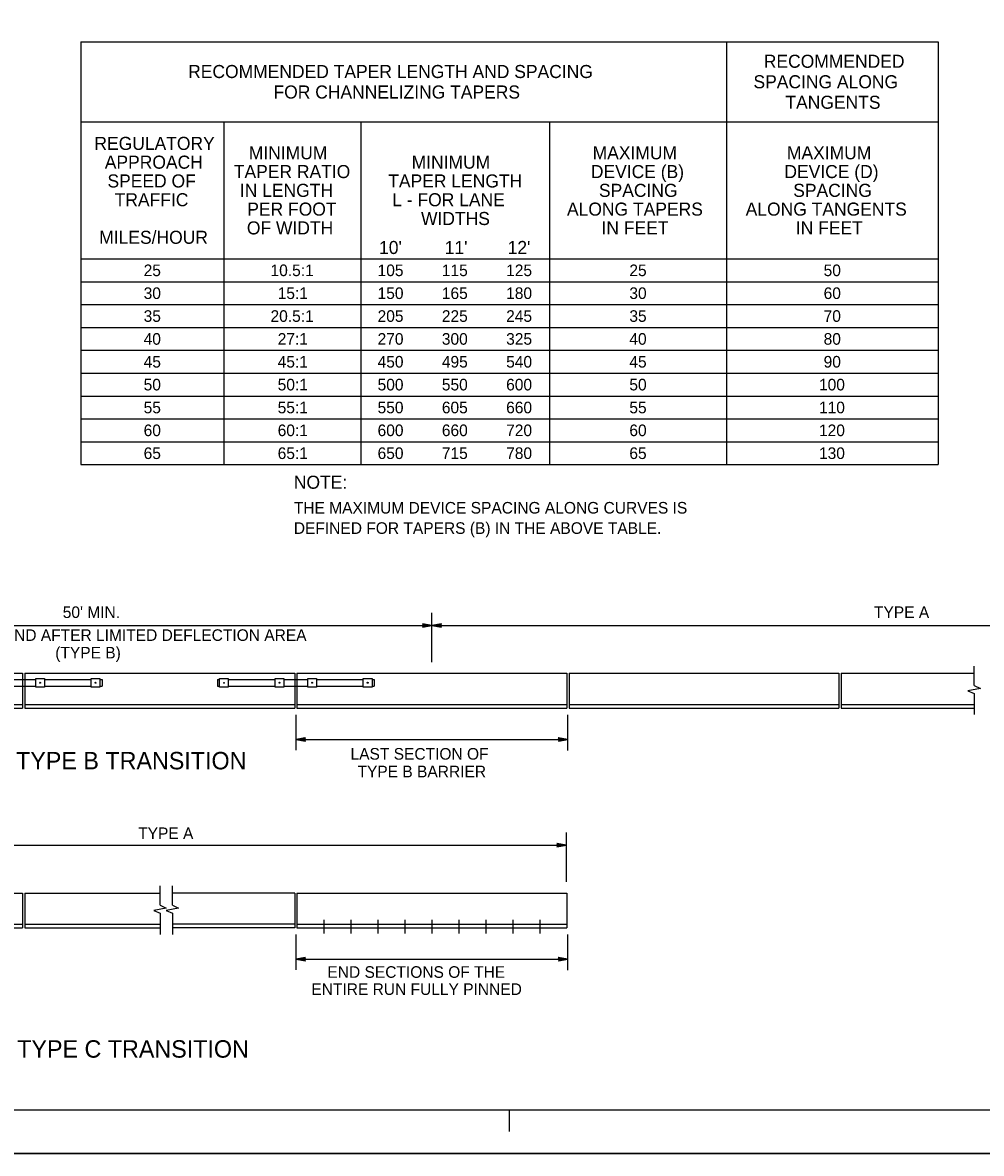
# Model space of a CAD drawing. Extents: x 499909 to 500993, y 502505 to 503165.
# Drawn here: x 500297.3 to 500627.6, y 502505 to 502894.5 of the extents above; entities that cross this region are included whole.
import ezdxf

# ---------------------------------------------------------------- set-up
doc = ezdxf.new("R2010")
doc.units = 0
for name, color, linetype in [('1', 7, 'Continuous'), ('24', 7, 'Continuous'), ('3', 7, 'Continuous'), ('39', 7, 'Continuous'), ('41', 7, 'Continuous'), ('5', 7, 'Continuous')]:
    doc.layers.add(name, color=color, linetype=linetype)

msp = doc.modelspace()

# ---------------------------------------------------------------- linework, layer by layer
at = {"layer": '1'}
for p, q in [((500000, 502520), (500990, 502520)), ((500465, 502512.5), (500465, 502520)), ((500993, 502505), (499944.83, 502505))]:
    msp.add_line(p, q, dxfattribs=at)
at = {"layer": '24'}
for points in [[(500438.31, 502686.89), (500434.99, 502687.48), (500435.78, 502686.89), (500435, 502686.31), (500438.31, 502686.89), (500438.09, 502686.88), (500435.08, 502687.43), (500435.84, 502686.88), (500435.14, 502686.36), (500437.97, 502686.87), (500437.86, 502686.89), (500435.28, 502687.35), (500435.86, 502686.88), (500435.26, 502686.43), (500437.81, 502686.89), (500437.7, 502686.87), (500435.44, 502687.28), (500435.88, 502686.89), (500435.44, 502686.48), (500437.38, 502686.87), (500437.19, 502686.87), (500435.61, 502687.2), (500435.92, 502686.9), (500435.59, 502686.57), (500437.16, 502686.89), (500436.98, 502686.9), (500435.79, 502687.1), (500436.02, 502686.87), (500435.77, 502686.64), (500436.82, 502686.89), (500436.65, 502686.91), (500435.94, 502687.04), (500436.05, 502686.88), (500435.86, 502686.7), (500436.56, 502686.89), (500436.1, 502687), (500436.16, 502686.87), (500435.96, 502686.75), (500436.45, 502686.87), (500436.14, 502686.95), (500436.27, 502686.85), (500436.12, 502686.79), (500436.27, 502686.88), (500436.19, 502686.9)], [(500438.31, 502686.89), (500441.63, 502686.3), (500440.84, 502686.89), (500441.62, 502687.47), (500438.31, 502686.89), (500438.53, 502686.9), (500441.54, 502686.34), (500440.78, 502686.9), (500441.48, 502687.42), (500438.65, 502686.91), (500438.76, 502686.89), (500441.34, 502686.43), (500440.76, 502686.9), (500441.36, 502687.35), (500438.81, 502686.89), (500438.92, 502686.91), (500441.18, 502686.5), (500440.74, 502686.89), (500441.19, 502687.29), (500439.24, 502686.91), (500439.43, 502686.91), (500441.01, 502686.58), (500440.7, 502686.88), (500441.03, 502687.21), (500439.46, 502686.89), (500439.64, 502686.88), (500440.83, 502686.68), (500440.6, 502686.91), (500440.85, 502687.13), (500439.8, 502686.89), (500439.97, 502686.87), (500440.68, 502686.74), (500440.57, 502686.9), (500440.76, 502687.07), (500440.06, 502686.89), (500440.52, 502686.78), (500440.46, 502686.91), (500440.66, 502687.03), (500440.18, 502686.91), (500440.48, 502686.83), (500440.35, 502686.93), (500440.5, 502686.99), (500440.35, 502686.9), (500440.43, 502686.88)], [(500391.37, 502647.58), (500394.7, 502646.99), (500393.9, 502647.58), (500394.68, 502648.16), (500391.37, 502647.58), (500391.6, 502647.59), (500394.61, 502647.04), (500393.84, 502647.59), (500394.55, 502648.11), (500391.71, 502647.6), (500391.82, 502647.58), (500394.4, 502647.12), (500393.82, 502647.59), (500394.42, 502648.04), (500391.88, 502647.58), (500391.99, 502647.6), (500394.24, 502647.19), (500393.8, 502647.58), (500394.25, 502647.98), (500392.31, 502647.6), (500392.49, 502647.6), (500394.07, 502647.27), (500393.77, 502647.57), (500394.1, 502647.9), (500392.53, 502647.58), (500392.71, 502647.57), (500393.89, 502647.37), (500393.66, 502647.6), (500393.91, 502647.82), (500392.87, 502647.58), (500393.04, 502647.56), (500393.75, 502647.43), (500393.63, 502647.59), (500393.83, 502647.76), (500393.12, 502647.58), (500393.59, 502647.47), (500393.52, 502647.6), (500393.72, 502647.72), (500393.24, 502647.6), (500393.54, 502647.52), (500393.42, 502647.62), (500393.56, 502647.68), (500393.42, 502647.59), (500393.49, 502647.57)], [(500485.15, 502647.58), (500481.83, 502648.17), (500482.62, 502647.58), (500481.85, 502647), (500485.15, 502647.58), (500484.93, 502647.57), (500481.92, 502648.12), (500482.69, 502647.57), (500481.98, 502647.05), (500484.82, 502647.56), (500484.7, 502647.58), (500482.13, 502648.04), (500482.7, 502647.57), (500482.11, 502647.12), (500484.65, 502647.58), (500484.54, 502647.56), (500482.29, 502647.97), (500482.73, 502647.58), (500482.28, 502647.17), (500484.22, 502647.56), (500484.03, 502647.56), (500482.46, 502647.89), (500482.76, 502647.59), (500482.43, 502647.26), (500484, 502647.58), (500483.82, 502647.59), (500482.64, 502647.79), (500482.86, 502647.56), (500482.62, 502647.33), (500483.66, 502647.58), (500483.49, 502647.6), (500482.78, 502647.73), (500482.9, 502647.57), (500482.7, 502647.39), (500483.41, 502647.58), (500482.94, 502647.69), (500483.01, 502647.56), (500482.8, 502647.44), (500483.29, 502647.56), (500482.98, 502647.64), (500483.11, 502647.54), (500482.97, 502647.48), (500483.11, 502647.57), (500483.03, 502647.59)], [(500484.68, 502611.2), (500481.35, 502611.79), (500482.15, 502611.2), (500481.37, 502610.62), (500484.68, 502611.2), (500484.46, 502611.19), (500481.45, 502611.74), (500482.21, 502611.19), (500481.5, 502610.67), (500484.34, 502611.18), (500484.23, 502611.2), (500481.65, 502611.66), (500482.23, 502611.19), (500481.63, 502610.74), (500484.18, 502611.2), (500484.07, 502611.18), (500481.81, 502611.59), (500482.25, 502611.2), (500481.8, 502610.8), (500483.74, 502611.18), (500483.56, 502611.18), (500481.98, 502611.51), (500482.29, 502611.21), (500481.96, 502610.88), (500483.52, 502611.2), (500483.35, 502611.21), (500482.16, 502611.41), (500482.39, 502611.18), (500482.14, 502610.96), (500483.18, 502611.2), (500483.02, 502611.22), (500482.3, 502611.35), (500482.42, 502611.19), (500482.23, 502611.02), (500482.93, 502611.2), (500482.46, 502611.31), (500482.53, 502611.18), (500482.33, 502611.06), (500482.81, 502611.18), (500482.51, 502611.26), (500482.63, 502611.16), (500482.49, 502611.1), (500482.63, 502611.19), (500482.56, 502611.21)], [(500391.37, 502571.89), (500394.7, 502571.3), (500393.9, 502571.89), (500394.68, 502572.47), (500391.37, 502571.89), (500391.6, 502571.9), (500394.61, 502571.35), (500393.84, 502571.9), (500394.55, 502572.42), (500391.71, 502571.91), (500391.82, 502571.89), (500394.4, 502571.43), (500393.82, 502571.9), (500394.42, 502572.35), (500391.88, 502571.89), (500391.99, 502571.91), (500394.24, 502571.5), (500393.8, 502571.89), (500394.25, 502572.3), (500392.31, 502571.91), (500392.49, 502571.91), (500394.07, 502571.58), (500393.77, 502571.88), (500394.1, 502572.21), (500392.53, 502571.89), (500392.71, 502571.88), (500393.89, 502571.68), (500393.66, 502571.91), (500393.91, 502572.14), (500392.87, 502571.89), (500393.04, 502571.87), (500393.75, 502571.74), (500393.63, 502571.9), (500393.83, 502572.08), (500393.12, 502571.89), (500393.59, 502571.78), (500393.52, 502571.91), (500393.72, 502572.03), (500393.24, 502571.91), (500393.54, 502571.83), (500393.42, 502571.93), (500393.56, 502571.99), (500393.42, 502571.9), (500393.49, 502571.88)], [(500485.15, 502571.89), (500481.83, 502572.48), (500482.62, 502571.89), (500481.85, 502571.31), (500485.15, 502571.89), (500484.93, 502571.88), (500481.92, 502572.43), (500482.69, 502571.88), (500481.98, 502571.36), (500484.82, 502571.87), (500484.7, 502571.89), (500482.13, 502572.35), (500482.7, 502571.88), (500482.11, 502571.43), (500484.65, 502571.89), (500484.54, 502571.87), (500482.29, 502572.28), (500482.73, 502571.89), (500482.28, 502571.49), (500484.22, 502571.87), (500484.03, 502571.87), (500482.46, 502572.2), (500482.76, 502571.9), (500482.43, 502571.57), (500484, 502571.89), (500483.82, 502571.9), (500482.64, 502572.1), (500482.86, 502571.87), (500482.62, 502571.65), (500483.66, 502571.89), (500483.49, 502571.91), (500482.78, 502572.04), (500482.9, 502571.88), (500482.7, 502571.71), (500483.41, 502571.89), (500482.94, 502572), (500483.01, 502571.87), (500482.8, 502571.75), (500483.29, 502571.87), (500482.98, 502571.95), (500483.11, 502571.85), (500482.97, 502571.79), (500483.11, 502571.88), (500483.03, 502571.9)]]:
    msp.add_lwpolyline(points, dxfattribs=at)
at = {"layer": '3'}
for p, q in [((500073.16, 502686.89), (500765.89, 502686.89)), ((500204.29, 502670.39), (500297.28, 502670.39)), ((500297.28, 502670.39), (500297.28, 502668.24)), ((500298.04, 502670.39), (500298.04, 502668.24)), ((500298.04, 502670.39), (500391.02, 502670.39)), ((500391.02, 502670.39), (500391.02, 502668.24)), ((500391.78, 502670.39), (500391.78, 502668.24)), ((500391.78, 502670.39), (500484.77, 502670.39)), ((500484.77, 502670.39), (500484.77, 502668.24)), ((500485.52, 502670.39), (500485.52, 502668.24)), ((500485.52, 502670.39), (500578.51, 502670.39)), ((500578.51, 502670.39), (500578.51, 502668.24)), ((500579.26, 502670.39), (500579.26, 502668.24)), ((500579.26, 502670.39), (500625.1, 502670.39)), ((500625.1, 502666.2), (500625.1, 502672.89)), ((500293.54, 502668.24), (500301.79, 502668.24)), ((500293.54, 502665.99), (500301.79, 502665.99)), ((500297.28, 502668.23), (500297.28, 502665.99)), ((500297.28, 502665.99), (500297.28, 502658.4)), ((500298.04, 502668.23), (500298.04, 502666)), ((500298.04, 502668.23), (500298.04, 502666)), ((500298.04, 502665.99), (500298.04, 502658.4)), ((500304.79, 502668.24), (500320.91, 502668.24)), ((500304.79, 502665.99), (500320.91, 502665.99)), ((500323.91, 502668.24), (500324.66, 502668.24)), ((500323.91, 502665.99), (500324.66, 502665.99)), ((500324.66, 502668.24), (500324.66, 502665.99)), ((500364.4, 502668.24), (500364.4, 502665.99)), ((500364.4, 502668.24), (500365.15, 502668.24)), ((500364.4, 502665.99), (500365.15, 502665.99)), ((500368.15, 502668.24), (500384.28, 502668.24)), ((500368.15, 502665.99), (500384.28, 502665.99)), ((500387.28, 502668.24), (500395.53, 502668.24)), ((500387.28, 502665.99), (500395.53, 502665.99)), ((500391.02, 502668.23), (500391.02, 502665.99)), ((500391.02, 502665.99), (500391.02, 502658.4)), ((500391.78, 502668.23), (500391.78, 502666)), ((500391.78, 502668.23), (500391.78, 502666)), ((500391.78, 502665.99), (500391.78, 502658.4)), ((500398.53, 502668.24), (500414.65, 502668.24)), ((500398.53, 502665.99), (500414.65, 502665.99)), ((500417.65, 502668.24), (500418.4, 502668.24)), ((500417.65, 502665.99), (500418.4, 502665.99)), ((500418.4, 502668.24), (500418.4, 502665.99)), ((500484.77, 502668.24), (500484.77, 502658.4)), ((500485.52, 502668.24), (500485.52, 502658.4)), ((500578.51, 502668.24), (500578.51, 502658.4)), ((500579.26, 502668.24), (500579.26, 502658.4)), ((500625.1, 502666.2), (500627.21, 502665.12)), ((500627.21, 502665.12), (500622.95, 502664.36)), ((500622.95, 502664.36), (500625.1, 502663.41)), ((500625.1, 502663.41), (500625.1, 502656.15)), ((500204.26, 502659.62), (500297.28, 502659.62)), ((500204.29, 502658.4), (500297.28, 502658.4)), ((500298.01, 502659.62), (500391.02, 502659.62)), ((500298.04, 502658.4), (500391.02, 502658.4)), ((500391.75, 502659.62), (500484.77, 502659.62)), ((500391.78, 502658.4), (500484.77, 502658.4)), ((500485.49, 502659.62), (500578.51, 502659.62)), ((500485.52, 502658.4), (500578.51, 502658.4)), ((500579.23, 502659.62), (500625.1, 502659.62)), ((500579.26, 502658.4), (500625.1, 502658.4)), ((500391.37, 502647.58), (500485.15, 502647.58)), ((500073.16, 502611.2), (500484.62, 502611.2)), ((500344.62, 502590.51), (500344.62, 502597.2)), ((500348.86, 502590.51), (500348.86, 502597.2)), ((500204.29, 502594.7), (500297.28, 502594.7)), ((500297.28, 502594.7), (500297.28, 502590.3)), ((500297.28, 502594.7), (500297.28, 502590.3)), ((500298.04, 502594.7), (500298.04, 502590.31)), ((500298.04, 502594.7), (500298.04, 502590.31)), ((500298.04, 502594.7), (500344.62, 502594.7)), ((500391.02, 502594.7), (500348.86, 502594.7)), ((500391.02, 502594.7), (500391.02, 502592.55)), ((500391.02, 502594.7), (500391.02, 502592.55)), ((500391.02, 502592.55), (500391.02, 502582.71)), ((500391.02, 502592.55), (500391.02, 502582.71)), ((500391.78, 502594.7), (500484.77, 502594.7)), ((500391.78, 502594.7), (500391.78, 502592.55)), ((500391.78, 502592.55), (500391.78, 502582.71)), ((500484.77, 502594.7), (500484.77, 502592.55)), ((500484.77, 502592.55), (500484.77, 502582.71)), ((500297.28, 502590.3), (500297.28, 502582.71)), ((500297.28, 502590.3), (500297.28, 502582.71)), ((500298.04, 502590.31), (500298.04, 502582.71)), ((500298.04, 502590.31), (500298.04, 502582.71)), ((500346.72, 502589.43), (500342.47, 502588.67)), ((500342.47, 502588.67), (500344.62, 502587.72)), ((500344.62, 502590.51), (500346.72, 502589.43)), ((500344.62, 502587.72), (500344.62, 502580.46)), ((500350.97, 502589.43), (500346.71, 502588.67)), ((500346.71, 502588.67), (500348.86, 502587.72)), ((500348.86, 502590.51), (500350.97, 502589.43)), ((500348.86, 502587.72), (500348.86, 502580.46)), ((500204.26, 502583.93), (500297.28, 502583.93)), ((500298.01, 502583.93), (500344.62, 502583.93)), ((500391.05, 502583.93), (500348.86, 502583.93)), ((500391.75, 502583.93), (500484.77, 502583.93)), ((500401.08, 502585.47), (500401.08, 502580.76)), ((500410.37, 502585.47), (500410.37, 502580.76)), ((500419.67, 502585.47), (500419.67, 502580.76)), ((500428.97, 502585.47), (500428.97, 502580.76)), ((500438.27, 502585.47), (500438.27, 502580.76)), ((500447.57, 502585.47), (500447.57, 502580.76)), ((500456.86, 502585.47), (500456.86, 502580.76)), ((500466.16, 502585.47), (500466.16, 502580.76)), ((500475.46, 502585.47), (500475.46, 502580.76)), ((500204.29, 502582.71), (500297.28, 502582.71)), ((500298.04, 502582.71), (500344.62, 502582.71)), ((500391.02, 502582.71), (500348.86, 502582.71)), ((500391.78, 502582.71), (500484.77, 502582.71)), ((500391.37, 502571.89), (500485.15, 502571.89))]:
    msp.add_line(p, q, dxfattribs=at)
for points in [[(500301.79, 502668.62), (500304.79, 502668.62), (500304.79, 502665.62), (500301.79, 502665.62)], [(500320.91, 502668.62), (500323.91, 502668.62), (500323.91, 502665.62), (500320.91, 502665.62)], [(500365.15, 502668.62), (500368.15, 502668.62), (500368.15, 502665.62), (500365.15, 502665.62)], [(500384.28, 502668.62), (500387.28, 502668.62), (500387.28, 502665.62), (500384.28, 502665.62)], [(500395.53, 502668.62), (500398.53, 502668.62), (500398.53, 502665.62), (500395.53, 502665.62)], [(500414.65, 502668.62), (500417.65, 502668.62), (500417.65, 502665.62), (500414.65, 502665.62)]]:
    msp.add_lwpolyline(points, close=True, dxfattribs=at)
for centre, radius in [((500303.29, 502667.12), 0.164), ((500322.41, 502667.12), 0.164), ((500366.65, 502667.12), 0.141), ((500385.78, 502667.12), 0.164), ((500397.03, 502667.12), 0.164), ((500416.15, 502667.12), 0.164)]:
    msp.add_circle(centre, radius, dxfattribs=at)
at = {"layer": '41'}
for p, q in [((500391.02, 502594.7), (500348.86, 502594.7)), ((500391.02, 502583.93), (500348.86, 502583.93)), ((500391.02, 502582.71), (500348.86, 502582.71))]:
    msp.add_line(p, q, dxfattribs=at)
msp.add_lwpolyline([(499944.83, 502505), (500993, 502505), (500993, 503165), (499944.83, 503165)], close=True, dxfattribs=at)
at = {"layer": '5'}
for p, q in [((500317.37, 502887.95), (500612.65, 502887.95)), ((500317.37, 502887.95), (500317.37, 502742.28)), ((500539.81, 502887.95), (500539.81, 502742.28)), ((500612.65, 502887.95), (500612.65, 502742.28)), ((500317.37, 502860.39), (500612.65, 502860.39)), ((500366.58, 502860.39), (500366.58, 502742.28)), ((500413.83, 502860.39), (500413.83, 502742.28)), ((500478.79, 502860.39), (500478.79, 502742.28)), ((500317.37, 502813.14), (500612.65, 502813.14)), ((500317.37, 502805.27), (500612.65, 502805.27)), ((500317.37, 502797.39), (500612.65, 502797.39)), ((500317.37, 502789.52), (500612.65, 502789.52)), ((500317.37, 502781.65), (500612.65, 502781.65)), ((500317.37, 502773.77), (500612.65, 502773.77)), ((500317.37, 502765.9), (500612.65, 502765.9)), ((500317.37, 502758.02), (500612.65, 502758.02)), ((500317.37, 502750.15), (500612.65, 502750.15)), ((500317.37, 502742.28), (500612.65, 502742.28)), ((500438.3, 502674.24), (500438.3, 502691.19)), ((500391.47, 502643.93), (500391.47, 502656.12)), ((500485.11, 502643.84), (500485.11, 502656.12)), ((500484.68, 502598.55), (500484.68, 502615.5)), ((500391.47, 502568.24), (500391.47, 502580.43)), ((500485.11, 502568.15), (500485.11, 502580.43))]:
    msp.add_line(p, q, dxfattribs=at)

# ---------------------------------------------------------------- texts
at = {"layer": '1'}
for s, height, p in [('RECOMMENDED TAPER LENGTH AND SPACING', 4.5, (500354.31, 502875.45)), ('RECOMMENDED', 4.5, (500552.62, 502878.98)), ('SPACING ALONG', 4.5, (500549.06, 502871.92)), ('FOR CHANNELIZING TAPERS', 4.5, (500383.71, 502868.39)), ('TANGENTS', 4.5, (500560.06, 502864.86)), ('REGULATORY', 4.5, (500322.01, 502850.69)), ('APPROACH', 4.5, (500325.59, 502844.22)), ('MINIMUM', 4.5, (500375.2, 502847.45)), ('MINIMUM', 4.5, (500431.3, 502844.22)), ('MAXIMUM', 4.5, (500493.65, 502847.45)), ('MAXIMUM', 4.5, (500560.58, 502847.45)), ('TAPER RATIO', 4.5, (500370.04, 502840.98)), ('DEVICE (B)', 4.5, (500493.04, 502840.98)), ('DEVICE (D)', 4.5, (500559.71, 502840.98)), ('SPEED OF', 4.5, (500326.51, 502837.75)), ('TAPER LENGTH', 4.5, (500423.24, 502837.75)), ('IN LENGTH', 4.5, (500372.13, 502834.51)), ('SPACING', 4.5, (500495.82, 502834.51)), ('SPACING', 4.5, (500562.75, 502834.51)), ('TRAFFIC ', 4.5, (500328.99, 502831.28)), ('L - FOR LANE', 4.5, (500424.61, 502831.28)), ('PER FOOT', 4.5, (500374.67, 502828.05)), ('WIDTHS', 4.5, (500434.53, 502824.81)), ('ALONG TAPERS', 4.5, (500484.81, 502828.05)), ('ALONG TANGENTS', 4.5, (500546.37, 502828.05)), ('OF WIDTH', 4.5, (500374.54, 502821.58)), ('IN FEET', 4.5, (500496.71, 502821.58)), ('IN FEET', 4.5, (500563.64, 502821.58)), ('MILES/HOUR', 4.5, (500323.68, 502818.34)), ('THE MAXIMUM DEVICE SPACING ALONG CURVES IS ', 4, (500390.72, 502725.41)), ('DEFINED FOR TAPERS (B) IN THE ABOVE TABLE.', 4, (500390.72, 502718.41)), ("50' MIN.", 4, (500311.11, 502689.44)), ('TYPE A', 4, (500590.57, 502689.44)), ('EXTEND BOX BEAM BEFORE AND AFTER LIMITED DEFLECTION AREA', 4, (500214.69, 502681.54)), ('(TYPE B)', 4, (500308.53, 502675.49)), ('CONNECTION TYPE B TRANSITION', 6, (500238.87, 502637.3)), ('LAST SECTION OF ', 4, (500410.25, 502640.64)), ('TYPE B BARRIER', 4, (500412.65, 502634.56)), ('TYPE A', 4, (500337.09, 502613.27)), ('END SECTIONS OF THE ', 4, (500402.29, 502565.48)), ('ENTIRE RUN FULLY PINNED', 4, (500396.75, 502559.58)), ('CONNECTION TYPE C TRANSITION', 6, (500239.26, 502537.98))]:
    msp.add_text(s, height=height, dxfattribs=at).set_placement(p)
at = {"layer": '39'}
msp.add_text('NOTE:', height=4.5, dxfattribs=at).set_placement((500390.72, 502733.96))
at = {"layer": '5'}
for s, height, p in [("10'", 4.5, (500420.08, 502814.83)), ("11'", 4.5, (500442.7, 502814.83)), ("12'", 4.5, (500464.37, 502814.83)), ('25', 4, (500338.98, 502807.21)), ('10.5:1', 4, (500382.69, 502807.21)), ('105', 4, (500419.57, 502807.21)), ('115', 4, (500441.71, 502807.21)), ('125', 4, (500463.86, 502807.21)), ('25', 4, (500506.3, 502807.21)), ('50', 4, (500573.23, 502807.21)), ('30', 4, (500338.98, 502799.33)), ('15:1', 4, (500385.15, 502799.33)), ('150', 4, (500419.57, 502799.33)), ('165', 4, (500441.71, 502799.33)), ('180', 4, (500463.86, 502799.33)), ('30', 4, (500506.3, 502799.33)), ('60', 4, (500573.23, 502799.33)), ('35', 4, (500338.98, 502791.46)), ('20.5:1', 4, (500382.69, 502791.46)), ('205', 4, (500419.57, 502791.46)), ('225', 4, (500441.71, 502791.46)), ('245', 4, (500463.86, 502791.46)), ('35', 4, (500506.3, 502791.46)), ('70', 4, (500573.23, 502791.46)), ('40', 4, (500338.98, 502783.58)), ('27:1', 4, (500385.15, 502783.58)), ('270', 4, (500419.57, 502783.58)), ('300', 4, (500441.71, 502783.58)), ('325', 4, (500463.86, 502783.58)), ('40', 4, (500506.3, 502783.58)), ('80', 4, (500573.23, 502783.58)), ('45', 4, (500338.98, 502775.71)), ('45:1', 4, (500385.15, 502775.71)), ('450', 4, (500419.57, 502775.71)), ('495', 4, (500441.71, 502775.71)), ('540', 4, (500463.86, 502775.71)), ('45', 4, (500506.3, 502775.71)), ('90', 4, (500573.23, 502775.71)), ('50', 4, (500338.98, 502767.84)), ('50:1', 4, (500385.15, 502767.84)), ('500', 4, (500419.57, 502767.84)), ('550', 4, (500441.71, 502767.84)), ('600', 4, (500463.86, 502767.84)), ('50', 4, (500506.3, 502767.84)), ('100', 4, (500571.63, 502767.84)), ('55', 4, (500338.98, 502759.96)), ('55:1', 4, (500385.15, 502759.96)), ('550', 4, (500419.57, 502759.96)), ('605', 4, (500441.71, 502759.96)), ('660', 4, (500463.86, 502759.96)), ('55', 4, (500506.3, 502759.96)), ('110', 4, (500571.63, 502759.96)), ('60', 4, (500338.98, 502752.09)), ('60:1', 4, (500385.15, 502752.09)), ('600', 4, (500419.57, 502752.09)), ('660', 4, (500441.71, 502752.09)), ('720', 4, (500463.86, 502752.09)), ('60', 4, (500506.3, 502752.09)), ('120', 4, (500571.63, 502752.09)), ('65', 4, (500338.98, 502744.21)), ('65:1', 4, (500385.15, 502744.21)), ('650', 4, (500419.57, 502744.21)), ('715', 4, (500441.71, 502744.21)), ('780', 4, (500463.86, 502744.21)), ('65', 4, (500506.3, 502744.21)), ('130', 4, (500571.63, 502744.21))]:
    msp.add_text(s, height=height, dxfattribs=at).set_placement(p)

doc.saveas('drawing.dxf')
